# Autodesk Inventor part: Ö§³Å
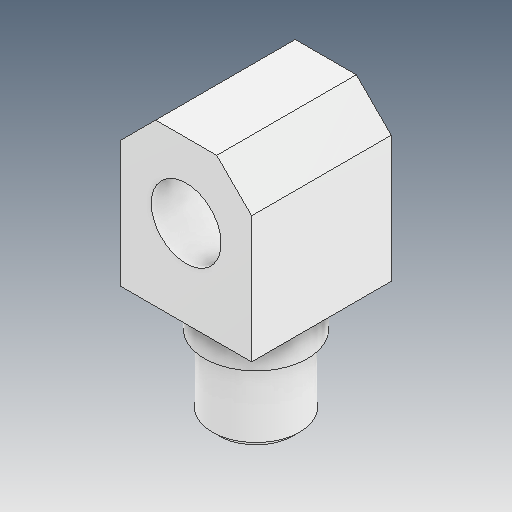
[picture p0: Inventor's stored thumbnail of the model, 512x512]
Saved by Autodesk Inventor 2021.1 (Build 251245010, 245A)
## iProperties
Created: 2021-05
Part Number: Ö§³Å
Material: Ogólny
Document SubType Name: Modeling
Designer: user
Density: 1 g/cm^3
Appearance: Domyślna
Author: user
Revision Number: ÈÎºÎ
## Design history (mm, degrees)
feature "ÊäÈë1"
node "Bryła1"
